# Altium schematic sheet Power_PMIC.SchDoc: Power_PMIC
size A3; Date: 01-DEC-2013; CompanyName: STMicroelectronics; Organization: Microcontrollers Division; Address1: 12, Rue Jules HOROWITZ; Address2: 38019 Grenoble; Address3: FRANCE; DocumentNumber: MB1272; Revision: A-01; SheetNumber: 5; SheetTotal: 15; Project: STM32MP15-DISCO PI
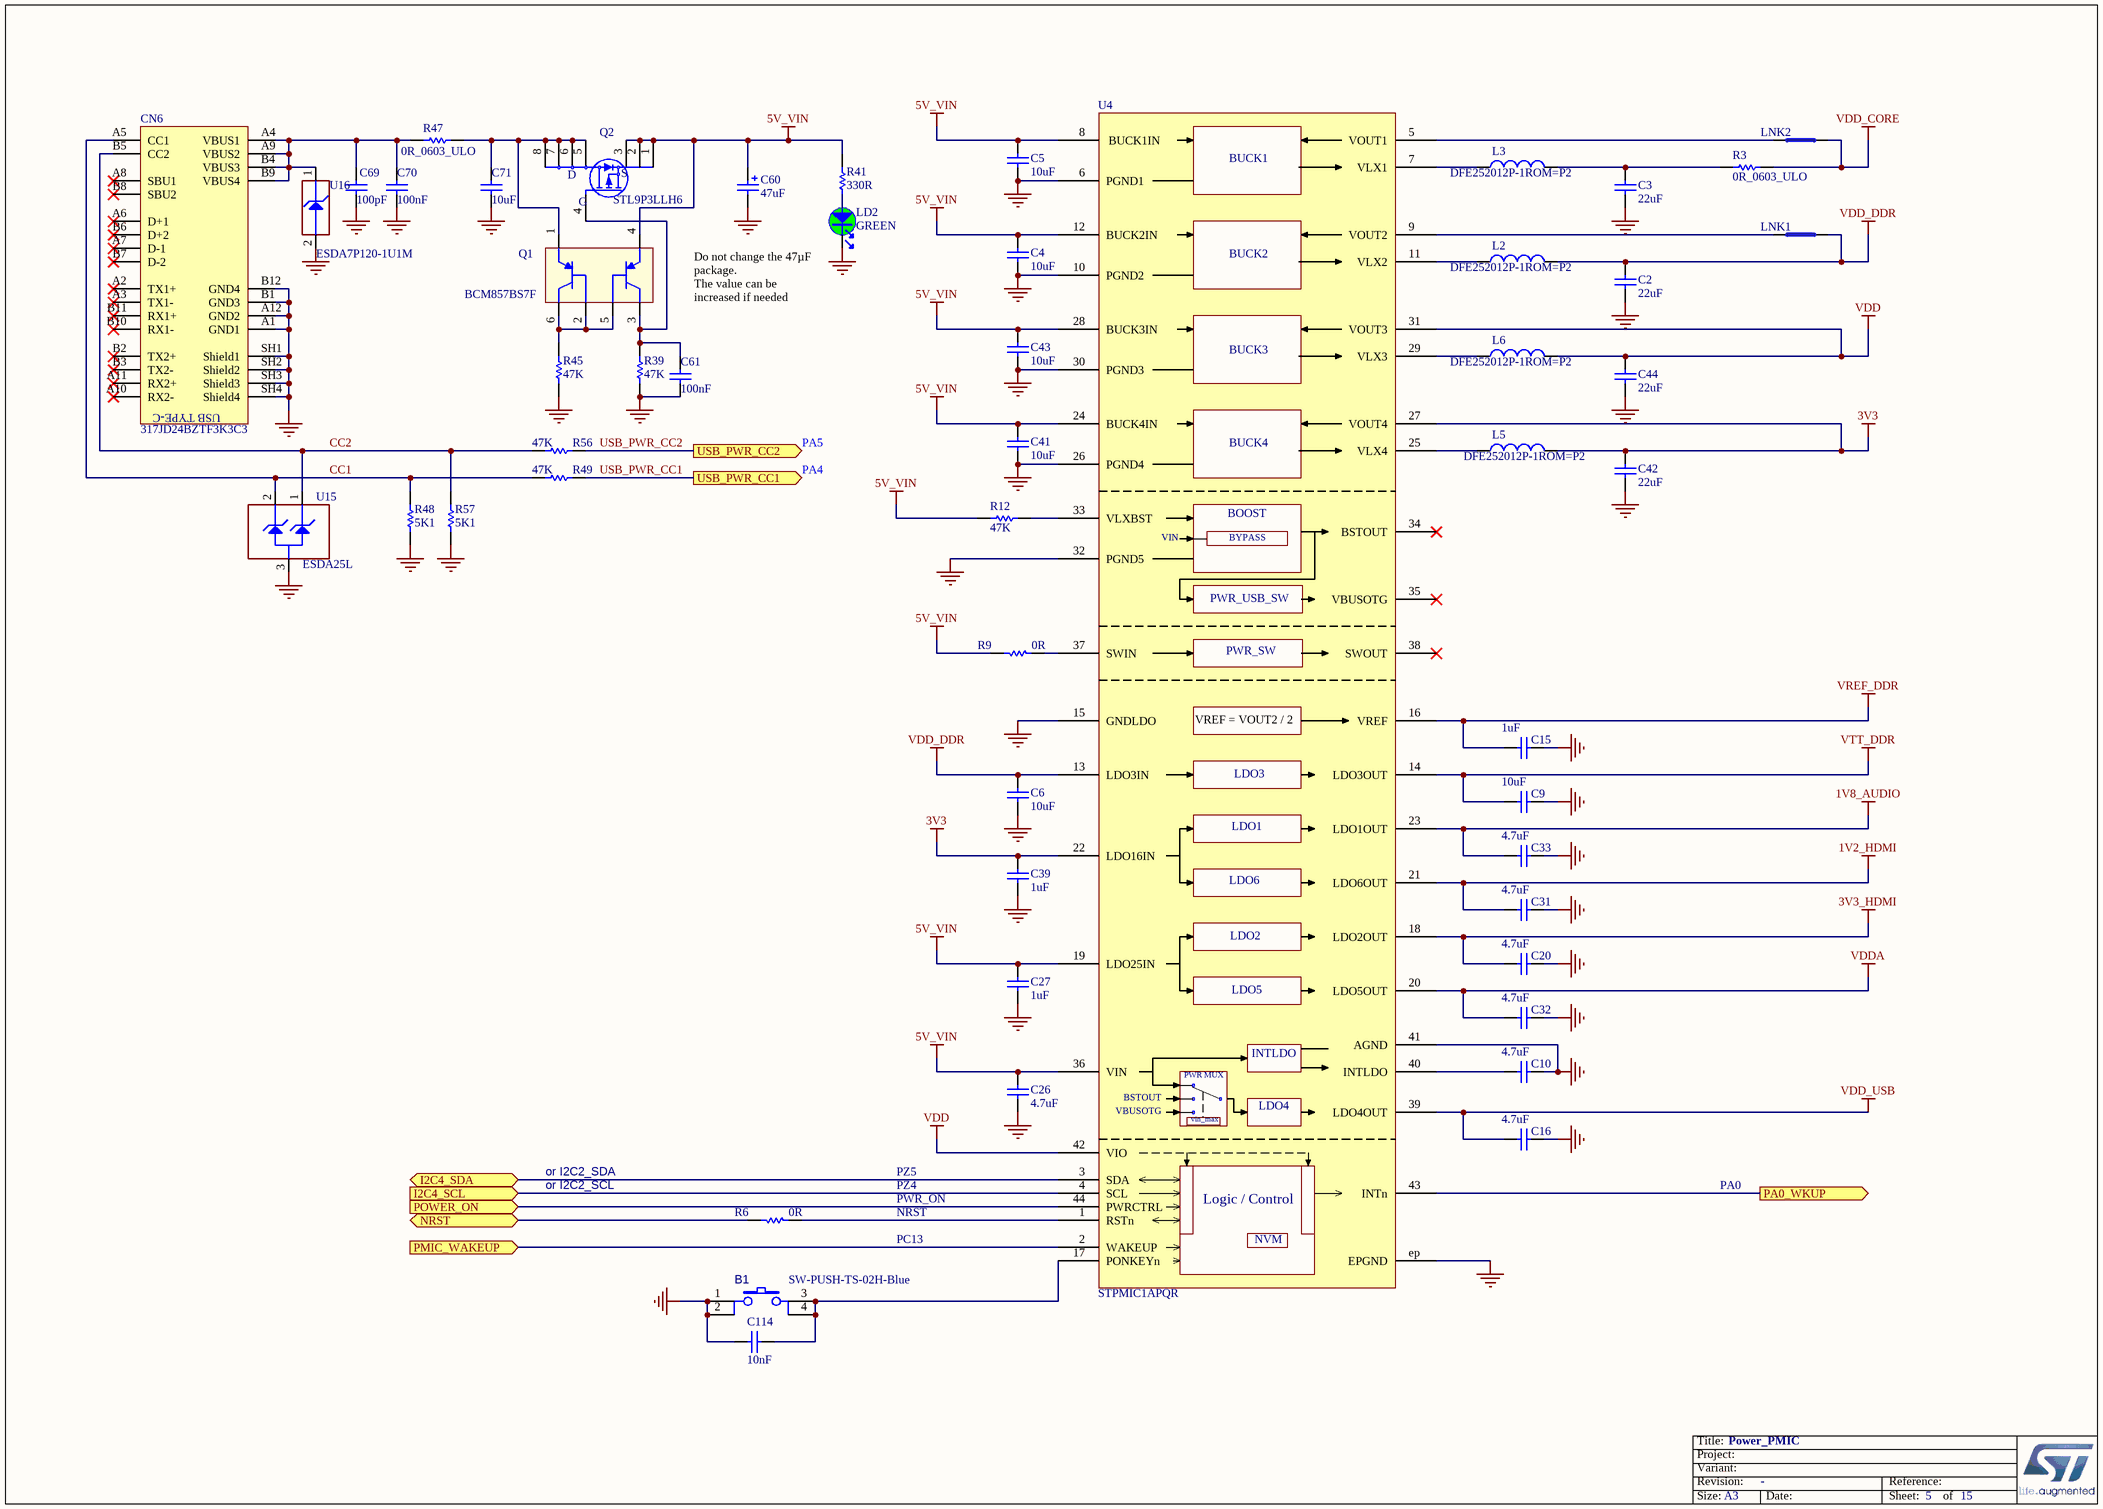
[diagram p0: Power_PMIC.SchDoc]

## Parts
B1  value SW-PUSH-TS-02H-Blue  [SWI_JIUBABA_C-TS-02H-2-5-B-V-T_R_BLUE]
C2  value 22uF  [C0603]
C3  value 22uF  [C0603]
C4  value 10uF  [C0603]
C5  value 10uF  [C0603]
C6  value 10uF  [C0603]
C9  value 10uF  [C0603]
C10  value 4.7uF  [C0402]  (hidden comment: Capacitor)
C15  value 1uF  [C0402]
C16  value 4.7uF  [C0402]  (hidden comment: Capacitor)
C20  value 4.7uF  [C0402]  (hidden comment: Capacitor)
C26  value 4.7uF  [C0402]  (hidden comment: Capacitor)
C27  value 1uF  [C0402]
C31  value 4.7uF  [C0402]  (hidden comment: Capacitor)
C32  value 4.7uF  [C0402]  (hidden comment: Capacitor)
C33  value 4.7uF  [C0402]  (hidden comment: Capacitor)
C39  value 1uF  [C0402]
C41  value 10uF  [C0603]
C42  value 22uF  [C0603]
C43  value 10uF  [C0603]
C44  value 22uF  [C0603]
C60  value 47uF  [CPOL_TAJ-C_2312_H2P6]  (hidden comment: Cap_POL_TANA)
C61  value 100nF  [C0402]
C69  value 100pF  [C0402]  (hidden comment: Capacitor)
C70  value 100nF  [C0402]
C71  value 10uF  [C0805]  (hidden comment: Capacitor)
C114  value 10nF  [C0402]
CN6  value 317JD24BZTF3K3C3  [CON_USB-TYPEC_COXOC_317JD24BZTF3K3C3]
L2  Manufacturer_Part_Number: DFE252012P-1ROM=P2  [IND_2520_TOKO_DFE252012P]  (hidden comment: IND_1uH_42mohm_3.2A)
L3  Manufacturer_Part_Number: DFE252012P-1ROM=P2  [IND_2520_TOKO_DFE252012P]  (hidden comment: IND_1uH_42mohm_3.2A)
L5  Manufacturer_Part_Number: DFE252012P-1ROM=P2  [IND_2520_TOKO_DFE252012P]  (hidden comment: IND_1uH_42mohm_3.2A)
L6  Manufacturer_Part_Number: DFE252012P-1ROM=P2  [IND_2520_TOKO_DFE252012P]  (hidden comment: IND_1uH_42mohm_3.2A)
LD2  value GREEN  [LED_0603_GREEN]
LNK1  link_200  [LINK200]  (value not drawn)  (no BOM)
LNK2  link_200  [LINK200]  (value not drawn)  (no BOM)
Q1  value BCM857BS7F  [DIO_SOT363]
Q2  value STL9P3LLH6  [MOS_POWERFLAT_3P3X3P3_P065]
R3  value 0R_0603_ULO  [R0603]
R6  value 0R  [R0402]
R9  value 0R  [R0402]
R12  value 47K  [R0402]  (hidden comment: Resistor)
R39  value 47K  [R0402]  (hidden comment: Resistor)
R41  value 330R  [R0402]
R45  value 47K  [R0402]  (hidden comment: Resistor)
R47  value 0R_0603_ULO  [R0603]
R48  value 5K1  [R0402]  (hidden comment: Resistor)
R49  value 47K  [R0402]  (hidden comment: Resistor)
R56  value 47K  [R0402]  (hidden comment: Resistor)
R57  value 5K1  [R0402]  (hidden comment: Resistor)
U4  value STPMIC1APQR  [ICC_WFQFN44-EPAD_5X6_P040]  (hidden comment: STPMU1)
U15  value ESDA25L  [ESD_SOT23]  (hidden comment: New schematic symbol : correction 2 diodes instead of one)
U16  value ESDA7P120-1U1M  [ESD_QFN1610_2N_1K_2A]  (hidden comment: ​Footprint needed DFN105P160X60-2N)

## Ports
I2C4_SCL (in), I2C4_SDA (bidir), NRST (bidir), PA0_WKUP (out), PMIC_WAKEUP (in), POWER_ON (in), USB_PWR_CC1 (out), USB_PWR_CC2 (out)

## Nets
1V2_HDMI: C31.2 U4.21(LDO6OUT)
1V8_AUDIO: C33.2 U4.23(LDO1OUT)
3V3: C39.2 C42.2 L5.2 U4.22(LDO16IN) U4.27(VOUT4)
3V3_HDMI: C20.2 U4.18(LDO2OUT)
5V_VIN: C4.2 C5.2 C26.2 C27.2 C41.2 C43.2 C60.1 Q1.4(E2) Q2.1(S) Q2.2(S) Q2.3(S) R9.1 R12.2 R41.2 U4.8(BUCK1IN) U4.12(BUCK2IN) U4.19(LDO25IN) U4.24(BUCK4IN) U4.28(BUCK3IN) U4.36(VIN)
GND: B1.1 B1.2 C2.1 C3.1 C4.1 C5.1 C6.1 C9.1 C10.2 C15.1 C16.1 C20.1 C26.1 C27.1 C31.1 C32.1 C33.1 C39.1 C41.1 C42.1 C43.1 C44.1 C60.2 C61.2 C69.1 C70.2 C71.1 C114.1 CN6.A1(GND1) CN6.A12(GND2) CN6.B1(GND3) CN6.B12(GND4) CN6.SH1(Shield1) CN6.SH2(Shield2) CN6.SH3(Shield3) CN6.SH4(Shield4) LD2.2 R39.1 R45.1 R48.1 R57.1 U4.6(PGND1) U4.10(PGND2) U4.15(GNDLDO) U4.26(PGND4) U4.30(PGND3) U4.32(PGND5) U4.41(AGND) U4.ep(EPGND) U15.3(GND) U16.2(GND)
VDD: C44.2 L6.2 U4.31(VOUT3) U4.42(VIO)
VDD_CORE: LNK2.2 R3.2
VDD_DDR: C2.2 C6.2 L2.2 LNK1.2 U4.13(LDO3IN)
VDD_USB: C16.2 U4.39(LDO4OUT)
VDDA: C32.2 U4.20(LDO5OUT)
VREF_DDR: C15.2 U4.16(VREF)
VTT_DDR: C9.2 U4.14(LDO3OUT)
CC1: CN6.A5(CC1) R48.2 R49.1 U15.2(IO2)
CC2: CN6.B5(CC2) R56.1 R57.2 U15.1(IO1)
I2C4_SCL: U4.4(SCL) ; port I2C4_SCL
I2C4_SDA: U4.3(SDA) ; port I2C4_SDA
NRST: R6.1 ; port NRST
PA0_WKUP: U4.43(INTn) ; port PA0_WKUP
PMIC_WAKEUP: U4.2(WAKEUP) ; port PMIC_WAKEUP
POWER_ON: U4.44(PWRCTRL) ; port POWER_ON
USB_PWR_CC1: R49.2 ; port USB_PWR_CC1
USB_PWR_CC2: R56.2 ; port USB_PWR_CC2
NetB1_3: B1.3 B1.4 C114.2 U4.17(PONKEYn)
NetC3_2: C3.2 L3.2 R3.1
NetC10_1: C10.1 U4.40(INTLDO)
NetC61_1: C61.1 Q1.3(C2) Q2.4(G) R39.2
NetC69_2: C69.2 C70.1 CN6.A4(VBUS1) CN6.A9(VBUS2) CN6.B4(VBUS3) CN6.B9(VBUS4) R47.1 U16.1(IO1)
NetC71_2: C71.2 Q1.1(E1) Q2.5(D) Q2.6(D) Q2.7(D) Q2.8(D) R47.2
NetL2_1: L2.1 U4.11(VLX2)
NetL3_1: L3.1 U4.7(VLX1)
NetL5_1: L5.1 U4.25(VLX4)
NetL6_1: L6.1 U4.29(VLX3)
NetLD2_1: LD2.1 R41.1
NetLNK1_1: LNK1.1 U4.9(VOUT2)
NetLNK2_1: LNK2.1 U4.5(VOUT1)
NetQ1_2: Q1.2(B1) Q1.5(B2) Q1.6(C1) R45.2
NetR6_2: R6.2 U4.1(RSTn)
NetR9_2: R9.2 U4.37(SWIN)
NetR12_1: R12.1 U4.33(VLXBST)

Not connected (* = marked no-connect by the designer): CN6 A2(TX1+)* A3(TX1-)* A6(D+1)* A7(D-1)* A8(SBU1)* A10(RX2-)* A11(RX2+)* B2(TX2+)* B3(TX2-)* B6(D+2)* B7(D-2)* B8(SBU2)* B10(RX1-)* B11(RX1+)*; U4 34(BSTOUT)* 35(VBUSOTG)* 38(SWOUT)*

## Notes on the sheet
- (near LD2) Do not change the 47µF package.
  The value can be increased if needed
- PA5
- PA4
- or I2C2_SDA
- or I2C2_SCL
- PZ5
- PZ4
- PA0
- NRST
- PWR_ON
- PC13

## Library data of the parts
B1 = MCD-00172: Switch HW SMD blue; Part_Type: Misc; Manufacturer_Part_Number: C-TS-02H-2.5-B-V-T/R BLUE; Manufacturer: JIUBABA; Provided_By: SUBCO; Initial_Board_Reference: MB1264
C2 C3 C42 C44 = MCD-00100: Capacitor, MLCC, 22uF, 6V3, X5R, 20%, 0603, T=0,8mm; Manufacturer_Part_Number: GRM188R60J226MEA0J; Manufacturer: MURATA; ECCN_US: EAR99; ECCN_EU: NEC; Provided_By: SUBCO; Initial_Board_Reference: mb1262
C4-C6 C9 C41 C43 = MCD-00099: Capacitor, MLCC, 10uF, 10V, X5R, 10%, 0603, T=0,8mm; Manufacturer_Part_Number: GRM188R61A106KE69D; Manufacturer: MURATA; ECCN_US: EAR99; ECCN_EU: NEC; Provided_By: SUBCO; Initial_Board_Reference: mb1262
C10 C16 C20 C26 C31-C33 = MCD-01356: Capacitor, MLCC, 4.7uF, 6V3, X5R, 20%, 0402, T=0,5mm; Manufacturer_Part_Number: GRM155R60J475ME47; Manufacturer: MURATA; Provided_By: SUBCO
C15 C27 C39 = MCD-00095: Capacitor, MLCC, 1uF, 6V3, X5R, 10%, 0402, T=0,5mm; Manufacturer_Part_Number: GRM155R61E105KA12; Manufacturer: MURATA; Alternate_Manufacturer_Part_Number: GRM155R60J105KE19; ECCN_US: EAR99; ECCN_EU: NEC; Provided_By: SUBCO; Initial_Board_Reference: mb1262
C60 = MCD-00559: Capacitor, Tantalum, 47uF, 16V, 10%, TypeC; Manufacturer_Part_Number: TAJC476K016RNJ; Manufacturer: AVX; Provided_By: SUBCO; Initial_Board_Reference: MB1331
C61 C70 = MCD-00006: Capacitor,100nF,16V,X7R,10%,0402; Manufacturer_Part_Number: CC0402KRX7R7BB104; Manufacturer: YAGEO; Alternate_Manufacturer: MURATA; Alternate_Manufacturer_Part_Number: GCM155R71C104KA55D; Provided_By: SUBCO; Initial_Board_Reference: mb1274
C69 = MCD-00205: Capacitor, MLCC, 100pF, 50V, NPO, 5%, 0402, T=0,5mm; Manufacturer_Part_Number: CC0402JRNPO9BN101; Manufacturer: YAGEO; Provided_By: SUBCO
C71 = MCD-00014: Capacitor, MLCC, 10uF, 25V, X5R, 10%, 0805, T=0,85mm; Manufacturer_Part_Number: CC0805KRX5R8BB106; Manufacturer: YAGEO; Provided_By: SUBCO; Initial_Board_Reference: MB1274
C114 = MCD-00011: Capacitor, MLCC, 10nF, 16V, X7R, 10%, 0402, T=0.5mm; Manufacturer_Part_Number: CC0402KRX7R7BB103; Manufacturer: YAGEO; Provided_By: SUBCO; Initial_Board_Reference: mb1274
CN6 = MCD-01108: USB tyce C certified receptacle for 1.6mm pcb height; Part_Type: Connector; Manufacturer: CHANT SINCERE (COXOC); ECCN_US: NA; Provided_By: SUBCO; Initial_Board_Reference: MB1272
L2 L3 L5 L6 = MCD-01122: Power Inductor ,1µH,4.3A max,+-20%,0.042ohm,2520; Manufacturer: MURATA; ECCN_US: EAR99; Provided_By: SUBCO; Initial_Board_Reference: MB1272
LD2 = MCD-00050: LED, Green, 0603; Part_Type: Display; Manufacturer_Part_Number: 19-213SYGC/S530-E2/TR8; Manufacturer: EVERLIGHT; ECCN_US: EAR99; ECCN_EU: NEC; Provided_By: SUBCO; Initial_Board_Reference: mb1274
LNK1 LNK2 = link_200: link 0.2mm
Q1 = MCD-01120: Transistor 45V Matched Pair PNP small Signal transistor in SOT363; Part_Type: IC; Manufacturer: DIODES_INC; Alternate_Manufacturer_Part_Number: NST45010MW6T1G; Alternate_Manufacturer: ONSEMI; Provided_By: SUBCO; Initial_Board_Reference: MB1272
Q2 = MCD-01126: Power Mosfet, P-channel,VDS -30V,RDS 12mohm typ,ID -9A; Part_Type: IC; Manufacturer: STMICROELECTRONICS; ECCN_US: EAR99; ECCN_EU: NEC; Provided_By: SUBCO with ST control; Initial_Board_Reference: MB1272
R3 R47 = MCD-00181: Resistor,0R,0603,ULO; Manufacturer_Part_Number: PMR03EZPJ000; Manufacturer: ROHM; Provided_By: SUBCO
R6 R9 = MCD-00052: Resistor,0R,0402,5%,1/16W; Manufacturer_Part_Number: RC0402JR-070RL; Manufacturer: YAGEO; Provided_By: SUBCO; Initial_Board_Reference: mb1274
R12 R39 R45 R49 R56 = MCD-00063: Resistor,47K,0402,1%,1/16W; Manufacturer_Part_Number: RC0402FR-0747KL; Manufacturer: YAGEO; Provided_By: SUBCO; Initial_Board_Reference: MB1274
R41 = MCD-00062: Resistor,330R,0402,1%,1/16W; Manufacturer_Part_Number: RC0402FR-07330RL; Manufacturer: YAGEO; Provided_By: SUBCO; Initial_Board_Reference: mb1274
R48 R57 = MCD-00333: Resistor,5K1,0402,1%,1/16W; Manufacturer_Part_Number: RC0402FR-075K1L; Manufacturer: YAGEO; Provided_By: SUBCO; Initial_Board_Reference: MB1272
U4 = MCD-01650: ST PMIC:  4 step-down + 1 advanced boost SMPS, 6 LDOs, 2 pwr switches, DDR Vref, NVM option 'A' for IO@3.3V; Part_Type: IC; Manufacturer: STMICROELECTRONICS; Provided_By: SUBCO with ST control
U15 = MCD-01125: DUAL TRANSIL ARRAY FOR ESD PROTECTION; Part_Type: Diode; Manufacturer: STMICROELECTRONICS; BMS_Part_Number: 9151131; ECCN_US: EAR99; ECCN_EU: NEC; Provided_By: SUBCO with ST control; Initial_Board_Reference: MB1272
U16 = MCD-01026: High power transient voltage suppressor; Part_Type: Diode; Manufacturer: STMICROELECTRONICS; BMS_Part_Number: 9179046; ECCN_US: EAR99; ECCN_EU: NEC; Provided_By: SUBCO with ST control; Initial_Board_Reference: MB1378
